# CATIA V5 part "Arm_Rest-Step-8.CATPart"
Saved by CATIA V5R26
Part number: Arm_Rest
Bounding box of the stored display mesh (mm): x 743.798 to 1422.756, y -778.323 to -638.163, z 345.981 to 527.8
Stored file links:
  D:\LinkedIn Learning\NURBS\CATIA\Class Parts\Arm_Rest-Step-9.CATPart
  D:\LinkedIn Learning\NURBS\Arm_Rest.CATPart
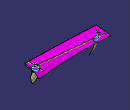
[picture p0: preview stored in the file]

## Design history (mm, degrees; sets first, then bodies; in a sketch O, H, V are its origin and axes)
AxisSystem1: origin (0, 0, 0), X (1, 0, 0), Y (0, 1, 0), Z (0, 0, 1)
StDynAnalysisRootNodeFeature1 "CATStDynAnalysisRootNodeName"
Set1 "REF DATA"
  CLDGeom1 "TOP"
  CLDGeom2 "FRONT"
  CLDGeom3 "AFT_BLEND"
  CLDGeom4 "END_AFT"
  CLDGeom5 "FORWARD_BLEND"
  CLDGeom6 "BOTTOM"
  CLDGeom7 "END_FORWARD"
  CLDGeom8 "UPPER_BLENDS"
  CLDGeom9 "LOWER_BLENDS"
  DatumSurface1 "DOOR_TRIM_SURFACE"
Set2 "FORM"
  Set3 "SLABS"
    DatumSurface2 to DatumSurface6
  Set4 "CURVES"
    St3DCurveFeature1 "CATSt3DCurveFeatureName": Order 6, CreationType 1, ClosureMode false, ConstructionPoints ({point type Coord, X 863.1168, Y 0, Z 551.1449}; {point type Coord, X 868.9503, Y 0, Z 330.43}), SymmetryMode false
    St3DCurveFeature2 "CATSt3DCurveFeatureName": Order 6, CreationType 1, ClosureMode false, ConstructionPoints ({point type Coord, X 1369.3867, Y 0, Z 551.9965}; {point type Coord, X 1358.4038, Y 0, Z 335.6826}), SymmetryMode false
    Intersect1: ToIntersect1 DatumSurface4, ToIntersect2 DatumSurface5
    Intersect2: ToIntersect1 DatumSurface6, ToIntersect2 DatumSurface4
    CurvePar1: Offset Intersect2, Support DatumSurface6, Offset2 0, Offset1 30
    CurvePar2: Offset Intersect1, Support DatumSurface5, Offset2 50, Offset1 20
    Project1: ToProject St3DCurveFeature1, Support DatumSurface4, Direction edge [YZ plane of AxisSystem1 | XY plane of AxisSystem1]
    Project2: ToProject St3DCurveFeature2, Support DatumSurface4, Direction edge [YZ plane of AxisSystem1 | XY plane of AxisSystem1]
    Project3: ToProject St3DCurveFeature2, Support StTopoTypeFeature3, Direction edge [YZ plane of AxisSystem1 | XY plane of AxisSystem1]
    Project4: ToProject St3DCurveFeature1, Support StTopoTypeFeature3, Direction edge [YZ plane of AxisSystem1 | XY plane of AxisSystem1]
    Intersect3: ToIntersect1 edge of StTopoTypeFeature1, ToIntersect2 CurvePar2
    Intersect4: ToIntersect1 edge of StTopoTypeFeature2, ToIntersect2 CurvePar1
    Project5: ToProject Intersect4, Support edge of StTopoTypeFeature2
    Project6: ToProject Intersect3, Support edge of StTopoTypeFeature1
    Line1: type PtPt, FirstPoint Intersect3, SecondPoint Project6, Support StTopoTypeFeature1
    Line2: type PtPt, FirstPoint Intersect4, SecondPoint Project5, Support StTopoTypeFeature2
    Curve1: Elements (Intersect4; vertex of Project3), Support Blend2
    Curve2: Elements (Project5; vertex of Project3), Support DatumSurface2
    Curve3: Elements (vertex of Project4; Intersect3), Support Blend1
    Curve4: Elements (vertex of Project4; Project6), Support DatumSurface2
  Set5 "BLENDS"
    Blend1: StartLimit {blendlimit Curve Project1, Support DatumSurface4, TensionValues 1.1}, EndLimit {blendlimit Curve CurvePar2, Support DatumSurface5, TensionValues 1}
    Blend2: StartLimit {blendlimit Curve CurvePar1, Support DatumSurface6, TensionValues 0.9}, EndLimit {blendlimit Curve Project2, Support DatumSurface4, TensionValues 0.8}
    StTopoTypeFeature1 "CATStTopoTypeFeatureName": Children 15
    StTopoTypeFeature2 "CATStTopoTypeFeatureName": Children 35
    StTopoTypeFeature3 "CATStTopoTypeFeatureName": nls://CATStFeaturesStartUpsNLS/TopoVarRadiCke 35, nls://CATStFeaturesStartUpsNLS/TopoVarRadiCke 15
    Loft1: Sections (Line2; Project3), StartSectionTangent StTopoTypeFeature2, EndSectionTangent StTopoTypeFeature3, Guides ({loftguide GuideCurve Curve1, GuideTangent Blend2}; {loftguide GuideCurve Curve2, GuideTangent DatumSurface2})
    Loft2: Sections (Project4; Line1), StartSectionTangent StTopoTypeFeature3, EndSectionTangent StTopoTypeFeature1, Guides ({loftguide GuideCurve Curve3, GuideTangent Blend1}; {loftguide GuideCurve Curve4, GuideTangent DatumSurface2})
Body1 (main body)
